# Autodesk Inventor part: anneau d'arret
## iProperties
Created: 2001-11
Part Number: anneau d'arret
Material: Par défaut
Document SubType Name: Modélisation
Designer: User
Control State: 0
Master: False
Checked Out: False
Shininess: 20.0
Length Units: 11269
Angle Units: 11279
Time Units: 11290
Mass Units: 11283
Length Display Precision: 3
Angle Display Precision: 2
Density: 0.0
Volumn: 0.0
Area: 0.0
PropertySet Name: Model Information
Author: User
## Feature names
1. Révolution1 [Revolution]
2. Extrusion1
